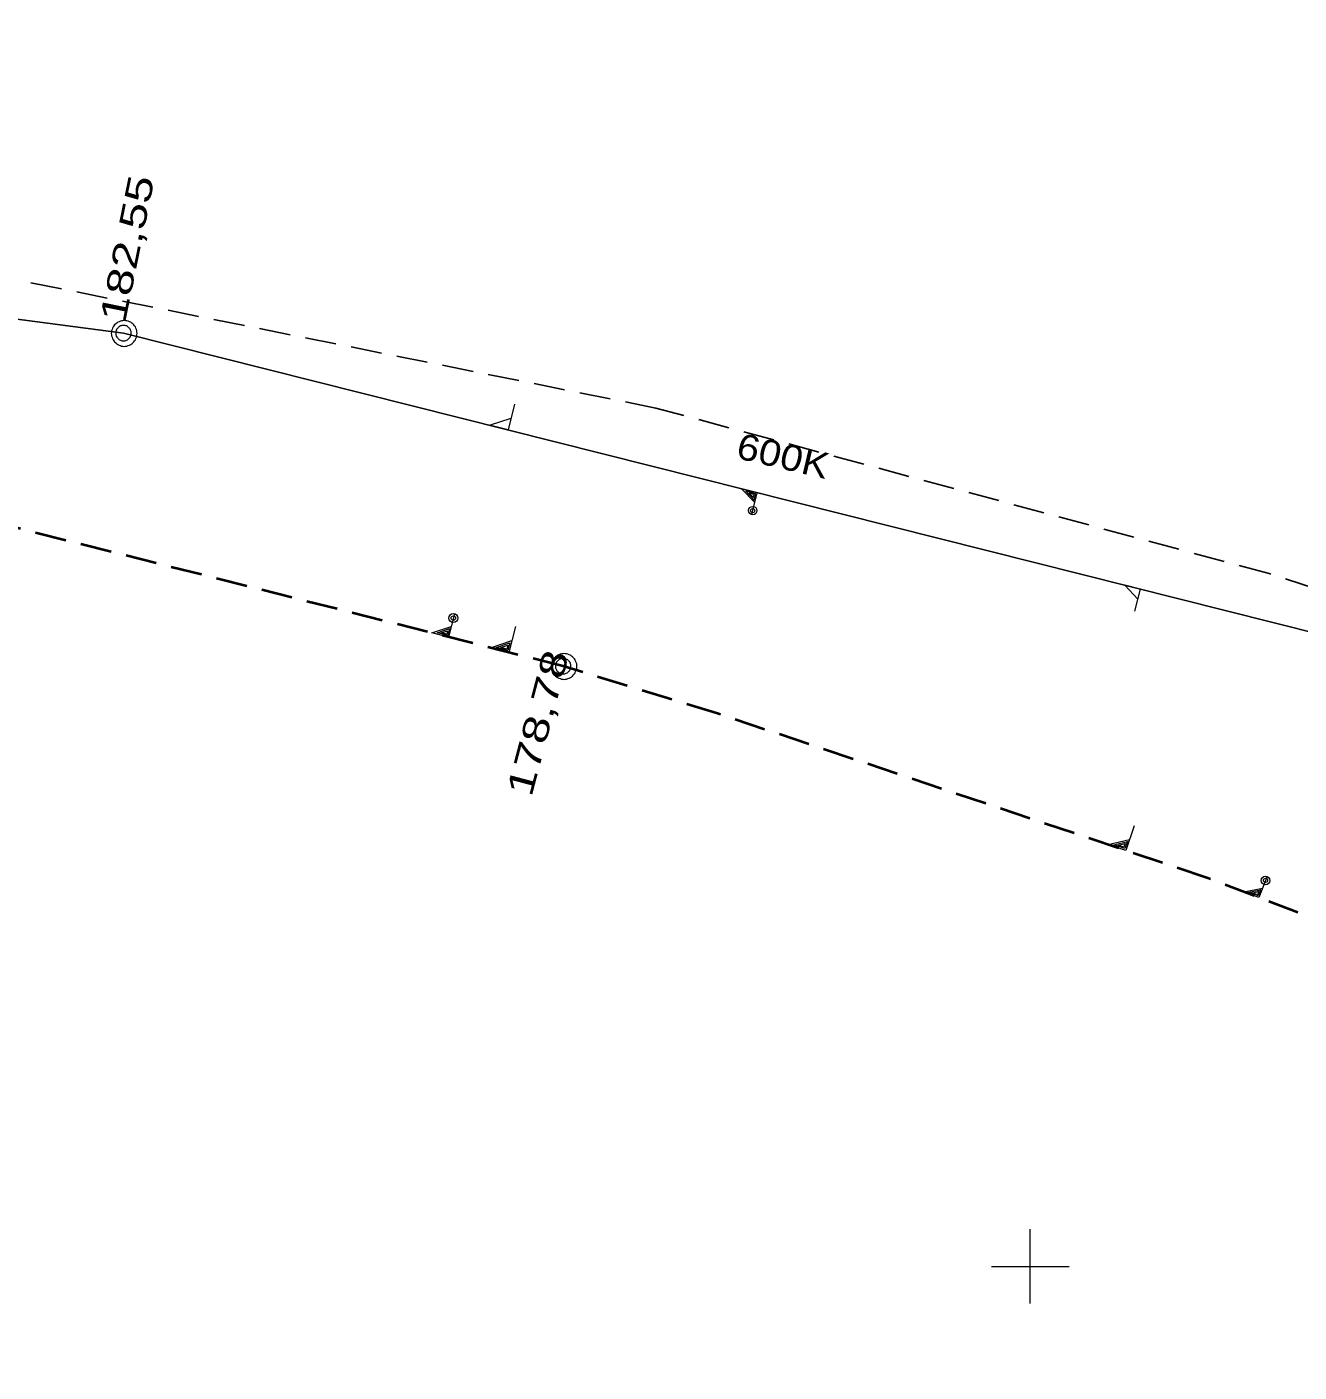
# Model space of a CAD drawing. Extents: x -740851 to -738888, y -1041382 to -1040235.
# Drawn here: x -739888.7 to -739839.6, y -1040504.1 to -1040452.2 of the extents above; entities that cross this region are included whole.
import ezdxf

# ---------------------------------------------------------------- set-up
doc = ezdxf.new("R2010")
doc.units = 0
doc.header["$LTSCALE"] = 0.4
doc.linetypes.add('MEDIUM_DASHED', pattern=[4.5, 3, -1.5])
for name, color, linetype, lineweight in [('1', 7, 'Continuous', 13), ('18', 7, 'Continuous', 13), ('8', 7, 'Continuous', 13)]:
    doc.layers.add(name, color=color, linetype=linetype, lineweight=lineweight)

msp = doc.modelspace()

# ---------------------------------------------------------------- linework, layer by layer
at = {"layer": '1'}
for p, q in [((-739850, -1040498.571), (-739850, -1040501.429)), ((-739851.48, -1040500), (-739848.48, -1040500))]:
    msp.add_line(p, q, dxfattribs=at)
at = {"layer": '18', "lineweight": 25}
msp.add_line((-739884.98, -1040463.99), (-739935.25, -1040457.45), dxfattribs=at)
at = {"layer": '18', "linetype": 'MEDIUM_DASHED', "lineweight": 40}
for points in [[(-739868.01, -1040476.84), (-739890.765, -1040471.085), (-739913.704, -1040466.108), (-739934.84, -1040462.24)], [(-739801.38, -1040504.08), (-739824.522, -1040492.113), (-739843.173, -1040485.007), (-739862.094, -1040478.655), (-739868.01, -1040476.84)]]:
    msp.add_lwpolyline(points, dxfattribs=at)
at = {"layer": '18'}
for points in [[(-739884.45, -1040464), (-739884.46, -1040463.95), (-739884.46, -1040463.9), (-739884.48, -1040463.85), (-739884.5, -1040463.8), (-739884.52, -1040463.75), (-739884.55, -1040463.71), (-739884.58, -1040463.67), (-739884.62, -1040463.63), (-739884.66, -1040463.6), (-739884.7, -1040463.57), (-739884.75, -1040463.55), (-739884.8, -1040463.53), (-739884.85, -1040463.51), (-739884.9, -1040463.51), (-739884.95, -1040463.5), (-739885, -1040463.51), (-739885.05, -1040463.51), (-739885.1, -1040463.53), (-739885.15, -1040463.55), (-739885.2, -1040463.57), (-739885.24, -1040463.6), (-739885.28, -1040463.63), (-739885.32, -1040463.67), (-739885.35, -1040463.71), (-739885.38, -1040463.75), (-739885.4, -1040463.8), (-739885.42, -1040463.85), (-739885.44, -1040463.9), (-739885.44, -1040463.95), (-739885.45, -1040464), (-739885.44, -1040464.05), (-739885.44, -1040464.1), (-739885.42, -1040464.15), (-739885.4, -1040464.2), (-739885.38, -1040464.25), (-739885.35, -1040464.29), (-739885.32, -1040464.33), (-739885.28, -1040464.37), (-739885.24, -1040464.4), (-739885.2, -1040464.43), (-739885.15, -1040464.45), (-739885.1, -1040464.47), (-739885.05, -1040464.49), (-739885, -1040464.49), (-739884.95, -1040464.5), (-739884.9, -1040464.49), (-739884.85, -1040464.49), (-739884.8, -1040464.47), (-739884.75, -1040464.45), (-739884.7, -1040464.43), (-739884.66, -1040464.4), (-739884.62, -1040464.37), (-739884.58, -1040464.33), (-739884.55, -1040464.29), (-739884.52, -1040464.25), (-739884.5, -1040464.2), (-739884.48, -1040464.15), (-739884.46, -1040464.1), (-739884.46, -1040464.05)], [(-739884.68, -1040463.99), (-739884.68, -1040463.96), (-739884.686, -1040463.93), (-739884.692, -1040463.9), (-739884.704, -1040463.87), (-739884.722, -1040463.84), (-739884.74, -1040463.816), (-739884.758, -1040463.792), (-739884.782, -1040463.768), (-739884.806, -1040463.75), (-739884.83, -1040463.732), (-739884.86, -1040463.714), (-739884.89, -1040463.702), (-739884.92, -1040463.696), (-739884.95, -1040463.69), (-739884.98, -1040463.69), (-739885.01, -1040463.69), (-739885.04, -1040463.696), (-739885.07, -1040463.702), (-739885.1, -1040463.714), (-739885.13, -1040463.732), (-739885.154, -1040463.75), (-739885.178, -1040463.768), (-739885.202, -1040463.792), (-739885.22, -1040463.816), (-739885.238, -1040463.84), (-739885.256, -1040463.87), (-739885.268, -1040463.9), (-739885.274, -1040463.93), (-739885.28, -1040463.96), (-739885.28, -1040463.99), (-739885.28, -1040464.02), (-739885.274, -1040464.05), (-739885.268, -1040464.08), (-739885.256, -1040464.11), (-739885.238, -1040464.14), (-739885.22, -1040464.164), (-739885.202, -1040464.188), (-739885.178, -1040464.212), (-739885.154, -1040464.23), (-739885.13, -1040464.248), (-739885.1, -1040464.266), (-739885.07, -1040464.278), (-739885.04, -1040464.284), (-739885.01, -1040464.29), (-739884.98, -1040464.29), (-739884.95, -1040464.29), (-739884.92, -1040464.284), (-739884.89, -1040464.278), (-739884.86, -1040464.266), (-739884.83, -1040464.248), (-739884.806, -1040464.23), (-739884.782, -1040464.212), (-739884.758, -1040464.188), (-739884.74, -1040464.164), (-739884.722, -1040464.14), (-739884.704, -1040464.11), (-739884.692, -1040464.08), (-739884.686, -1040464.05), (-739884.68, -1040464.02)], [(-739867.48, -1040476.85), (-739867.49, -1040476.8), (-739867.49, -1040476.75), (-739867.51, -1040476.7), (-739867.53, -1040476.65), (-739867.55, -1040476.6), (-739867.58, -1040476.56), (-739867.61, -1040476.52), (-739867.65, -1040476.48), (-739867.69, -1040476.45), (-739867.73, -1040476.42), (-739867.78, -1040476.4), (-739867.83, -1040476.38), (-739867.88, -1040476.36), (-739867.93, -1040476.36), (-739867.98, -1040476.35), (-739868.03, -1040476.36), (-739868.08, -1040476.36), (-739868.13, -1040476.38), (-739868.18, -1040476.4), (-739868.23, -1040476.42), (-739868.27, -1040476.45), (-739868.31, -1040476.48), (-739868.35, -1040476.52), (-739868.38, -1040476.56), (-739868.41, -1040476.6), (-739868.43, -1040476.65), (-739868.45, -1040476.7), (-739868.47, -1040476.75), (-739868.47, -1040476.8), (-739868.48, -1040476.85), (-739868.47, -1040476.9), (-739868.47, -1040476.95), (-739868.45, -1040477), (-739868.43, -1040477.05), (-739868.41, -1040477.1), (-739868.38, -1040477.14), (-739868.35, -1040477.18), (-739868.31, -1040477.22), (-739868.27, -1040477.25), (-739868.23, -1040477.28), (-739868.18, -1040477.3), (-739868.13, -1040477.32), (-739868.08, -1040477.34), (-739868.03, -1040477.34), (-739867.98, -1040477.35), (-739867.93, -1040477.34), (-739867.88, -1040477.34), (-739867.83, -1040477.32), (-739867.78, -1040477.3), (-739867.73, -1040477.28), (-739867.69, -1040477.25), (-739867.65, -1040477.22), (-739867.61, -1040477.18), (-739867.58, -1040477.14), (-739867.55, -1040477.1), (-739867.53, -1040477.05), (-739867.51, -1040477), (-739867.49, -1040476.95), (-739867.49, -1040476.9)], [(-739867.71, -1040476.84), (-739867.71, -1040476.81), (-739867.716, -1040476.78), (-739867.722, -1040476.75), (-739867.734, -1040476.72), (-739867.752, -1040476.69), (-739867.77, -1040476.666), (-739867.788, -1040476.642), (-739867.812, -1040476.618), (-739867.836, -1040476.6), (-739867.86, -1040476.582), (-739867.89, -1040476.564), (-739867.92, -1040476.552), (-739867.95, -1040476.546), (-739867.98, -1040476.54), (-739868.01, -1040476.54), (-739868.04, -1040476.54), (-739868.07, -1040476.546), (-739868.1, -1040476.552), (-739868.13, -1040476.564), (-739868.16, -1040476.582), (-739868.184, -1040476.6), (-739868.208, -1040476.618), (-739868.232, -1040476.642), (-739868.25, -1040476.666), (-739868.268, -1040476.69), (-739868.286, -1040476.72), (-739868.298, -1040476.75), (-739868.304, -1040476.78), (-739868.31, -1040476.81), (-739868.31, -1040476.84), (-739868.31, -1040476.87), (-739868.304, -1040476.9), (-739868.298, -1040476.93), (-739868.286, -1040476.96), (-739868.268, -1040476.99), (-739868.25, -1040477.014), (-739868.232, -1040477.038), (-739868.208, -1040477.062), (-739868.184, -1040477.08), (-739868.16, -1040477.098), (-739868.13, -1040477.116), (-739868.1, -1040477.128), (-739868.07, -1040477.134), (-739868.04, -1040477.14), (-739868.01, -1040477.14), (-739867.98, -1040477.14), (-739867.95, -1040477.134), (-739867.92, -1040477.128), (-739867.89, -1040477.116), (-739867.86, -1040477.098), (-739867.836, -1040477.08), (-739867.812, -1040477.062), (-739867.788, -1040477.038), (-739867.77, -1040477.014), (-739867.752, -1040476.99), (-739867.734, -1040476.96), (-739867.722, -1040476.93), (-739867.716, -1040476.9), (-739867.71, -1040476.87)]]:
    msp.add_lwpolyline(points, close=True, dxfattribs=at)
at = {"layer": '18', "lineweight": 25}
msp.add_lwpolyline([(-739795.67, -1040490.17), (-739836.89, -1040476.1), (-739884.98, -1040463.99)], dxfattribs=at)
at = {"layer": '18'}
for points in [[(-739869.885, -1040466.725), (-739870.137, -1040467.725), (-739870.85, -1040467.546), (-739870.023, -1040467.274)], [(-739860.736, -1040470.99), (-739860.524, -1040470.148), (-739861.124, -1040469.997), (-739860.62, -1040470.528)], [(-739860.643, -1040470.432), (-739860.581, -1040470.188), (-739860.964, -1040470.091), (-739860.639, -1040470.434)], [(-739860.665, -1040470.333), (-739860.634, -1040470.211), (-739860.831, -1040470.161), (-739860.661, -1040470.334)], [(-739845.948, -1040474.72), (-739845.735, -1040473.873), (-739846.34, -1040473.72), (-739845.831, -1040474.255)], [(-739872.206, -1040474.821), (-739872.433, -1040475.719), (-739873.074, -1040475.557), (-739872.33, -1040475.314)], [(-739872.4, -1040475.392), (-739872.467, -1040475.654), (-739872.876, -1040475.55), (-739872.396, -1040475.393)], [(-739872.471, -1040475.474), (-739872.504, -1040475.605), (-739872.714, -1040475.552), (-739872.467, -1040475.476)], [(-739869.853, -1040475.308), (-739870.105, -1040476.308), (-739870.819, -1040476.127), (-739869.991, -1040475.856)], [(-739870.069, -1040475.943), (-739870.143, -1040476.235), (-739870.599, -1040476.119), (-739870.064, -1040475.945)], [(-739870.148, -1040476.035), (-739870.185, -1040476.181), (-739870.419, -1040476.122), (-739870.144, -1040476.036)], [(-739845.98, -1040483.002), (-739846.3, -1040483.955), (-739846.98, -1040483.726), (-739846.156, -1040483.525)], [(-739846.238, -1040483.604), (-739846.331, -1040483.881), (-739846.765, -1040483.735), (-739846.233, -1040483.605)], [(-739846.321, -1040483.687), (-739846.368, -1040483.826), (-739846.591, -1040483.751), (-739846.317, -1040483.688)], [(-739840.847, -1040484.956), (-739841.158, -1040485.772), (-739841.741, -1040485.551), (-739841.018, -1040485.404)], [(-739841.092, -1040485.47), (-739841.183, -1040485.707), (-739841.555, -1040485.566), (-739841.088, -1040485.471)], [(-739841.168, -1040485.539), (-739841.213, -1040485.658), (-739841.404, -1040485.585), (-739841.164, -1040485.541)]]:
    msp.add_lwpolyline(points, dxfattribs=at)
for centre, radius in [((-739860.697, -1040470.836), 0.163), ((-739860.699, -1040470.838), 0.0807), ((-739872.248, -1040474.986), 0.174), ((-739872.249, -1040474.985), 0.0862), ((-739840.905, -1040485.107), 0.165), ((-739840.905, -1040485.105), 0.0813)]:
    msp.add_circle(centre, radius, dxfattribs=at)
at = {"layer": '8', "linetype": 'MEDIUM_DASHED', "lineweight": 25}
msp.add_lwpolyline([(-739809.48, -1040483.712), (-739832.13, -1040476.03), (-739840.77, -1040473.27), (-739864.43, -1040466.88), (-739898.28, -1040460.1), (-739963.421, -1040452.173)], dxfattribs=at)

# ---------------------------------------------------------------- texts
at = {"layer": '18'}
for s, rotation, width, p in [('182,55', 78.451, 1.4, (-739884.923, -1040463.632)), ('600K', 346.811, 1.15, (-739861.385, -1040468.802)), ('178,78', 75.233, 1.4, (-739869.238, -1040481.924))]:
    msp.add_text(s, height=1, rotation=rotation, dxfattribs=dict(at, width=width)).set_placement(p)

doc.saveas('drawing.dxf')
